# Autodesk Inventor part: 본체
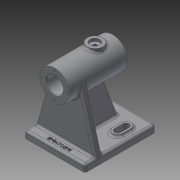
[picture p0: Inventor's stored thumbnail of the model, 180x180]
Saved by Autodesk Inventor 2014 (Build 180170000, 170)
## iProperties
Created: 2019-10
Part Number: 본체
Material: Generic
Document SubType Name: Modeling
Designer: kh
Density: 1 g/cm^3
Appearance: Default
Author: kh
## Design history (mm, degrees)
sketch "Sketch1"
  geometry: L1 (-41, 21)-(41, 21); L2 (41, 21)-(41, 0); L3 (41, 0)-(-41, 0); L4 (-41, 0)-(-41, 21); 2 further points
  constraints: 8 end point, 2 parallel, 1 coincident, 1 horizontal, 1 midpoint, 1 perpendicular
  dimensions: "d0" = 42 diameter of L1 L3; "d1" = 82 distance of L1.start L1.end
revolve "Revolution1" sketch "Sketch1" stored, may be unused: angle "d2" = 90 deg
sketch "Sketch2"
  geometry: L1 (41, -21)-(41, 21) reference; L2 (-41, -21)-(-41, 21) reference; L3 (-41, 0)-(21, 0); L4 (21, 0)-(21, 14.5); L5 (21, 14.5)-(-41, 14.5); L6 (-41, 14.5)-(-41, 0); L7 (21, 0)-(41, 0); L8 (41, 0)-(41, 11.5); L9 (41, 11.5)-(21, 11.5); L10 (21, 11.5)-(21, 0); 1 further point
  constraints: 16 end point, 4 parallel, 2 horizontal, 2 perpendicular, 1 midpoint, 1 point on line
  dimensions: "d3" = 29 diameter of L5 L3; "d4" = 23 diameter of L9 L7; "d5" = 62 distance of L4.end L5.end
revolve "Revolution2" sketch "Sketch2" stored, may be unused: angle "d6" = 90 deg
chamfer "Chamfer1" distance "d7" = 1; stored, may be unused: second distance "d8" = 2, angle "d9" = 45 deg
workplane "Work Plane1"
sketch "Sketch3"
  geometry: L1 (41, 21)-(41, -21) reference; C1 r 11 at (16, 0); 1 further point
  constraints: 1 centre point, 1 horizontal alignment
  dimensions: "d11" = 22 diameter of C1; "d12" = 25 distance from line of C1.centre L1
extrude "Extrusion1" join sketch "Sketch3" stored distance "d13" = 10; taper "d14" = 0 deg
hole "Hole1" diameter "d17" = 4.917; stored, may be unused: countersink angle "d21" = 90 deg, drill point angle "d23" = 0 deg; dims "d18" = 6, "d19" = 14, "d20" = 4, "d22" = 8, "d87" = 10, "d88" = 10
fillet "Fillet1" dims "d24" = 3
workplane "Work Plane2"
sketch "Sketch4"
  geometry: L1 (-41, 21)-(-41, -21) reference; L2 (-41, 43)-(59, 43); L3 (59, 43)-(59, -43); L4 (59, -43)-(-41, -43); L5 (-41, -43)-(-41, 43); L6 (0, 0)-(-41, 0)
  constraints: 10 end point, 2 parallel, 2 perpendicular, 1 horizontal, 1 midpoint, 1 point on line, 1 other
  dimensions: "d26" = 100 distance of L3.end L4.end; "d27" = 86 distance of L2.end L3.end
extrude "Extrusion2" join sketch "Sketch4" distance "d28" = 10; taper "d29" = 0 deg
fillet "Fillet2" dims "d38" = 3
fillet "Fillet3" dims "d39" = 3
sketch "Sketch7"
  geometry: 1 further point
workplane "Work Plane4"
  workplane "Work Plane3"
sketch "Sketch8"
  geometry: L1 (-40, -76)-(40, -76) reference; L2 (-42.896, -78.217)-(-20.272, 5.48); L3 (20.272, 5.48)-(42.896, -78.217); A1 r 21 centre (0, 0) between (-20.298, 5.385) and (20.298, 5.385) reference; A2 r 3 centre (40, -79) between (43, -79) and (40, -76) reference; A3 r 3 centre (-40, -79) between (-40, -76) and (-43, -79) reference; 3 further points
  constraints: 8 point on circle, 4 end point, 4 tangent
extrude "Extrusion4" join sketch "Sketch8" distance "d40" = 10; taper "d41" = 0 deg
sketch "Sketch9"
  geometry: L1 (31.598, -16.592)-(31.598, 16.592); L2 (31.598, 16.592)-(36.402, 16.592); L3 (36.402, 16.592)-(36.402, -16.592); L4 (36.402, -16.592)-(31.598, -16.592); L5 (31.598, -16.592)-(36.402, 16.592); L6 (-56, -43)-(38, -43) reference; L7 (41, -40)-(41, 40) reference; 2 further points
  constraints: 2 end point, 1 midpoint, 2 other
  dimensions: "d46" = 43 distance from line of point (34, 0) L6; "d47" = 7 distance from line of point (34, 0) L7
emboss "Emboss1" sketch "Sketch9" dims "d0" = 42, "d1" = 82, "d48" = 0.5, "d49" = 0
sketch "Sketch10" dims "d50" = 36
  geometry: C1 r 21 at (0, 0) reference; 3 further points
  constraints: 2 vertical alignment, 1 coincident, 2 other
hole "Hole2" sketch "Sketch10" at (0, 18) diameter "d51" = 2.459; stored, may be unused: countersink angle "d55" = 82 deg, drill point angle "d57" = 118 deg; dims "d52" = 8, "d53" = 3.023, "d54" = 4, "d56" = 10
pattern_circular "Circular Pattern1" dims angle "d59" = 360 deg
mirror "Mirror1"
sketch "Sketch11"
  geometry: L1 (-56, -76)-(38, -76) reference; L2 (-41, -21)-(41, -21) reference; L3 (-44, -76)-(-23.982, -21); L4 (-59, -86)-(-59, -79) reference; 2 further points
  constraints: 2 end point, 2 point on line
  dimensions: "d63" = 15 distance from line of L3.start L4; "d64" = 70 deg angle of L1 L3
feature "Rib1" sketch "Sketch11" dims "d65" = 1, "d66" = 10, "d67" = 0, "d68" = 0, "d69" = 1, "d70" = 1
fillet "Fillet11" dims "d72" = 3
fillet "Fillet12" dims "d73" = 3
sketch "Sketch12"
  geometry: L1 (-33, -27)-(-21, -27); L2 (-33, -31.5)-(-21, -31.5); L3 (-21, -22.5)-(-33, -22.5); L4 (-59, 40)-(-59, -40) reference; L5 (-21, -20)-(-33, -20); L6 (-33, -34)-(-21, -34); A1 r 4.5 centre (-33, -27) between (-33, -22.5) and (-33, -31.5); A2 r 4.5 centre (-21, -27) between (-21, -31.5) and (-21, -22.5); A3 r 7 centre (-33, -27) between (-33, -20) and (-33, -34); A4 r 7 centre (-21, -27) between (-21, -34) and (-21, -20); 2 further points
  constraints: 12 end point, 8 point on circle, 4 centre point, 4 tangent, 2 parallel, 1 horizontal, 1 midpoint, 3 other
  dimensions: "d75" = 12 distance of L1.end L1.start; "d77" = 9 distance between parallel lines of L2 L3; "d78" = 26 distance from line of L1.start L4; "d79" = 27 horizontal distance of point (0, 0) point (-27, -27); "d80" = 14 distance between parallel lines of L6 L5
extrude "Extrusion5" join sketch "Sketch12" distance "d81" = 3; taper "d82" = 0 deg
sketch "Sketch13"
  geometry: L1 (-33, -27)-(-21, -27); L2 (-33, -31.5)-(-21, -31.5); L3 (-21, -22.5)-(-33, -22.5); A1 r 7 centre (-21, -27) between (-21, -34) and (-21, -20) reference; A2 r 7 centre (-33, -27) between (-33, -20) and (-33, -34) reference; A3 r 4.5 centre (-33, -27) between (-33, -22.5) and (-33, -31.5); A4 r 4.5 centre (-21, -27) between (-21, -31.5) and (-21, -22.5); 2 further points
  constraints: 8 end point, 4 point on circle, 4 tangent, 2 centre point, 1 horizontal, 1 midpoint, 1 parallel
  dimensions: "d83" = 9 diameter of A4
extrude "Extrusion6" cut sketch "Sketch13" stored distance "d84" = 3; taper "d85" = 0 deg
fillet "Fillet13" dims "d86" = 3
mirror "Mirror2"
body "Solid1"
node "Projected Loop1"
other parameters: "d10" = 24, "d25" = -86, "d35" = -15
